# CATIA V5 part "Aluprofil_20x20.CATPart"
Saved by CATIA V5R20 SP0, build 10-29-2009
Part number: Aluprofil_20x20
Nomenclature: P20_N5_I
Source: Unknown
Bounding box of the stored display mesh (mm): x -13.375 to 6.625, y -20 to 0, z 0 to 304
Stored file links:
  C:\Users\Andi\Desktop\Offene Projekte\Plasmacutter\Z-Achse\Aluprofil_20x20.CATPart
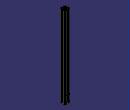
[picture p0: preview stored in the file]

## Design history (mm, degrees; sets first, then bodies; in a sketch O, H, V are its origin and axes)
Set1
  Sketch1 on face of Solid1, origin (0, 0, 1000), H (1, 0, 0), V (0, 1, 0)
    projected line E1 (0.275, -8.8654) -> (0.275, -11.1346) from edge [face of Solid1 | face of Solid1]
    projected arc E2 centre (3.275, -8.8654) radius 3 from (1.1537, -6.7441) to (0.275, -8.8654) ccw from edge [face of Solid1 | face of Solid1]
    projected line E3 (3.4935, -4.4043) -> (1.1537, -6.7441) from edge [face of Solid1 | face of Solid1]
    projected arc E4 centre (4.045, -4.9559) radius 0.78 from (4.825, -4.9559) to (3.4935, -4.4043) ccw from edge [face of Solid1 | face of Solid1]
    projected line E5 (4.825, -7.125) -> (4.825, -4.9559) from edge [face of Solid1 | face of Solid1]
    projected arc E6 centre (5.125, -7.125) radius 0.3 from (4.825, -7.125) to (5.125, -7.425) ccw from edge [face of Solid1 | face of Solid1]
    projected line E7 (5.825, -7.425) -> (5.125, -7.425) from edge [face of Solid1 | face of Solid1]
    projected arc E8 centre (5.825, -6.625) radius 0.8 from (5.825, -7.425) to (6.625, -6.625) ccw from edge [face of Solid1 | face of Solid1]
    projected line E9 (6.625, -2) -> (6.625, -6.625) from edge [face of Solid1 | face of Solid1]
    projected arc E10 centre (4.625, -2) radius 2 from (6.625, -2) to (4.625, 0) ccw from edge [face of Solid1 | face of Solid1]
    projected line E11 (0, 0) -> (4.625, 0) from edge [face of Solid1 | face of Solid1]
    projected arc E12 centre (0, -0.8) radius 0.8 from (0, 0) to (-0.8, -0.8) ccw from edge [face of Solid1 | face of Solid1]
    projected line E13 (-0.8, -1.5) -> (-0.8, -0.8) from edge [face of Solid1 | face of Solid1]
    projected arc E14 centre (-0.5, -1.5) radius 0.3 from (-0.8, -1.5) to (-0.5, -1.8) ccw from edge [face of Solid1 | face of Solid1]
    projected line E15 (1.6691, -1.8) -> (-0.5, -1.8) from edge [face of Solid1 | face of Solid1]
    projected arc E16 centre (1.6691, -2.58) radius 0.78 from (2.2207, -3.1315) to (1.6691, -1.8) ccw from edge [face of Solid1 | face of Solid1]
    projected line E17 (-0.1191, -5.4713) -> (2.2207, -3.1315) from edge [face of Solid1 | face of Solid1]
    projected arc E18 centre (-2.2404, -3.35) radius 3 from (-2.2404, -6.35) to (-0.1191, -5.4713) ccw from edge [face of Solid1 | face of Solid1]
    projected line E19 (-4.5096, -6.35) -> (-2.2404, -6.35) from edge [face of Solid1 | face of Solid1]
    projected arc E20 centre (-4.5096, -3.35) radius 3 from (-6.6309, -5.4713) to (-4.5096, -6.35) ccw from edge [face of Solid1 | face of Solid1]
    projected line E21 (-8.9707, -3.1315) -> (-6.6309, -5.4713) from edge [face of Solid1 | face of Solid1]
    projected arc E22 centre (-8.4191, -2.58) radius 0.78 from (-8.4191, -1.8) to (-8.9707, -3.1315) ccw from edge [face of Solid1 | face of Solid1]
    projected line E23 (-6.25, -1.8) -> (-8.4191, -1.8) from edge [face of Solid1 | face of Solid1]
    projected arc E24 centre (-6.25, -1.5) radius 0.3 from (-6.25, -1.8) to (-5.95, -1.5) ccw from edge [face of Solid1 | face of Solid1]
    projected line E25 (-5.95, -0.8) -> (-5.95, -1.5) from edge [face of Solid1 | face of Solid1]
    projected arc E26 centre (-6.75, -0.8) radius 0.8 from (-5.95, -0.8) to (-6.75, 0) ccw from edge [face of Solid1 | face of Solid1]
    projected line E27 (-11.375, 0) -> (-6.75, 0) from edge [face of Solid1 | face of Solid1]
    projected arc E28 centre (-11.375, -2) radius 2 from (-11.375, 0) to (-13.375, -2) ccw from edge [face of Solid1 | face of Solid1]
    projected line E29 (-13.375, -6.625) -> (-13.375, -2) from edge [face of Solid1 | face of Solid1]
    projected arc E30 centre (-12.575, -6.625) radius 0.8 from (-13.375, -6.625) to (-12.575, -7.425) ccw from edge [face of Solid1 | face of Solid1]
    projected line E31 (-11.875, -7.425) -> (-12.575, -7.425) from edge [face of Solid1 | face of Solid1]
    projected arc E32 centre (-11.875, -7.125) radius 0.3 from (-11.875, -7.425) to (-11.575, -7.125) ccw from edge [face of Solid1 | face of Solid1]
    projected line E33 (-11.575, -4.9559) -> (-11.575, -7.125) from edge [face of Solid1 | face of Solid1]
    projected arc E34 centre (-10.795, -4.9559) radius 0.78 from (-10.2435, -4.4043) to (-11.575, -4.9559) ccw from edge [face of Solid1 | face of Solid1]
    projected line E35 (-7.9037, -6.7441) -> (-10.2435, -4.4043) from edge [face of Solid1 | face of Solid1]
    projected arc E36 centre (-10.025, -8.8654) radius 3 from (-7.025, -8.8654) to (-7.9037, -6.7441) ccw from edge [face of Solid1 | face of Solid1]
    projected line E37 (-7.025, -11.1346) -> (-7.025, -8.8654) from edge [face of Solid1 | face of Solid1]
    projected arc E38 centre (-10.025, -11.1346) radius 3 from (-7.9037, -13.2559) to (-7.025, -11.1346) ccw from edge [face of Solid1 | face of Solid1]
    projected line E39 (-10.2435, -15.5957) -> (-7.9037, -13.2559) from edge [face of Solid1 | face of Solid1]
    projected arc E40 centre (-10.795, -15.0441) radius 0.78 from (-11.575, -15.0441) to (-10.2435, -15.5957) ccw from edge [face of Solid1 | face of Solid1]
    projected line E41 (-11.575, -12.875) -> (-11.575, -15.0441) from edge [face of Solid1 | face of Solid1]
    projected arc E42 centre (-11.875, -12.875) radius 0.3 from (-11.575, -12.875) to (-11.875, -12.575) ccw from edge [face of Solid1 | face of Solid1]
    projected line E43 (-12.575, -12.575) -> (-11.875, -12.575) from edge [face of Solid1 | face of Solid1]
    projected arc E44 centre (-12.575, -13.375) radius 0.8 from (-12.575, -12.575) to (-13.375, -13.375) ccw from edge [face of Solid1 | face of Solid1]
    projected line E45 (-13.375, -18) -> (-13.375, -13.375) from edge [face of Solid1 | face of Solid1]
    projected arc E46 centre (-11.375, -18) radius 2 from (-13.375, -18) to (-11.375, -20) ccw from edge [face of Solid1 | face of Solid1]
    projected line E47 (-6.75, -20) -> (-11.375, -20) from edge [face of Solid1 | face of Solid1]
    projected arc E48 centre (-6.75, -19.2) radius 0.8 from (-6.75, -20) to (-5.95, -19.2) ccw from edge [face of Solid1 | face of Solid1]
    projected line E49 (-5.95, -18.5) -> (-5.95, -19.2) from edge [face of Solid1 | face of Solid1]
    projected arc E50 centre (-6.25, -18.5) radius 0.3 from (-5.95, -18.5) to (-6.25, -18.2) ccw from edge [face of Solid1 | face of Solid1]
    projected line E51 (-8.4191, -18.2) -> (-6.25, -18.2) from edge [face of Solid1 | face of Solid1]
    projected arc E52 centre (-8.4191, -17.42) radius 0.78 from (-8.9707, -16.8685) to (-8.4191, -18.2) ccw from edge [face of Solid1 | face of Solid1]
    projected line E53 (-6.6309, -14.5287) -> (-8.9707, -16.8685) from edge [face of Solid1 | face of Solid1]
    projected arc E54 centre (-4.5096, -16.65) radius 3 from (-4.5096, -13.65) to (-6.6309, -14.5287) ccw from edge [face of Solid1 | face of Solid1]
    projected line E55 (-2.2404, -13.65) -> (-4.5096, -13.65) from edge [face of Solid1 | face of Solid1]
    projected arc E56 centre (-2.2404, -16.65) radius 3 from (-0.1191, -14.5287) to (-2.2404, -13.65) ccw from edge [face of Solid1 | face of Solid1]
    projected line E57 (2.2207, -16.8685) -> (-0.1191, -14.5287) from edge [face of Solid1 | face of Solid1]
    projected arc E58 centre (1.6691, -17.42) radius 0.78 from (1.6691, -18.2) to (2.2207, -16.8685) ccw from edge [face of Solid1 | face of Solid1]
    projected line E59 (-0.5, -18.2) -> (1.6691, -18.2) from edge [face of Solid1 | face of Solid1]
    projected arc E60 centre (-0.5, -18.5) radius 0.3 from (-0.5, -18.2) to (-0.8, -18.5) ccw from edge [face of Solid1 | face of Solid1]
    projected line E61 (-0.8, -19.2) -> (-0.8, -18.5) from edge [face of Solid1 | face of Solid1]
    projected arc E62 centre (0, -19.2) radius 0.8 from (-0.8, -19.2) to (0, -20) ccw from edge [face of Solid1 | face of Solid1]
    projected line E63 (4.625, -20) -> (0, -20) from edge [face of Solid1 | face of Solid1]
    projected arc E64 centre (4.625, -18) radius 2 from (4.625, -20) to (6.625, -18) ccw from edge [face of Solid1 | face of Solid1]
    projected line E65 (6.625, -13.375) -> (6.625, -18) from edge [face of Solid1 | face of Solid1]
    projected arc E66 centre (5.825, -13.375) radius 0.8 from (6.625, -13.375) to (5.825, -12.575) ccw from edge [face of Solid1 | face of Solid1]
    projected line E67 (5.125, -12.575) -> (5.825, -12.575) from edge [face of Solid1 | face of Solid1]
    projected arc E68 centre (5.125, -12.875) radius 0.3 from (5.125, -12.575) to (4.825, -12.875) ccw from edge [face of Solid1 | face of Solid1]
    projected line E69 (4.825, -15.0441) -> (4.825, -12.875) from edge [face of Solid1 | face of Solid1]
    projected arc E70 centre (4.045, -15.0441) radius 0.78 from (3.4935, -15.5957) to (4.825, -15.0441) ccw from edge [face of Solid1 | face of Solid1]
    projected line E71 (1.1537, -13.2559) -> (3.4935, -15.5957) from edge [face of Solid1 | face of Solid1]
    projected arc E72 centre (3.275, -11.1346) radius 3 from (0.275, -11.1346) to (1.1537, -13.2559) ccw from edge [face of Solid1 | face of Solid1]
    projected arc E73 centre (-3.375, -10) radius 2.15 from (-5.525, -10) to (-1.225, -10) ccw from edge [face of Solid1 | face of Solid1]
    projected arc E74 centre (-3.375, -10) radius 2.15 from (-1.225, -10) to (-5.525, -10) ccw from edge [face of Solid1 | face of Solid1]
Body1 "MANIFOLD_SOLID_BREP #2567" (main body)
  Solid1: solid without history
  Pocket1: profile Sketch1, direction (0, 0, -1), length 696
  Sketch2 on face of Solid1, origin (-3.1428, 0, 12.5455), H (1, 0, 0), V (0, 0, -1)
    point P1 (-0.2322, 6.5455)
    reference intersected line E1 through (0, 12.5455) direction (1, 0) from face of Solid1
    reference intersected line E2 through (-10.2322, 0) direction (0, -1) from face of Solid1
    reference intersected line E3 through (9.7678, 0) direction (0, 1) from face of Solid1
    distance P1 E1 = 6
    equidistance: E2 E3 P1
  Hole1: placed by Sketch2, at (-3.375, 0, 6) direction (0, -1, 0), diameter 5.5, through (limit type 6), counterbore diameter 9.5, counterbore depth 6.35
  RectPattern1: of Hole1, direction 1 instances 2, spacing 23, along face of Solid1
